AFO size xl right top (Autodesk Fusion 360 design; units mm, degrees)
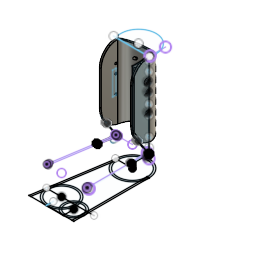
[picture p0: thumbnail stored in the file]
part number: 2025-10-02-12-56-12-317
parameter "d73" = 49
parameter "d131" = 16
sketch "Sketch1" plane through (0, 0, 0) normal (0, 0, 1) x axis (1, 0, 0)
  line L1 (28, -127.4) -> (-48, -127.4)
  line L2 (28, 0) -> (28, -127.4)
  line L3 (25, 0) -> (25, -127.4)
  line L4 (28, 0) -> (25, 0)
  line L5 (-18.603, -127.4) -> (-18.603, -115.6)
  line L6 (10.5, -127.4) -> (10.5, -109.9)
  line L7 (10.5, -127.4) -> (-18.603, -127.4)
  line L8 (36.7314, -101.9) -> (-43.9969, -101.9)
  line L9 (0, 0) -> (-28.984, 0)
  line L10 (-45, -127.4) -> (-25, 0)
  line L11 (-40.9969, -101.9) -> (-44.0794, -101.4161)
  line L12 (-48, -127.4) -> (-28, 0)
  line L13 (-43.6846, -101.9) -> (-43.6828, -102.2021)
  circle C1 centre (0, 0) radius 28
  circle C2 centre (0, 0) radius 25
  circle C3 centre (10.5, -109.9) radius 17.5
  circle C4 centre (-18.1846, -101.9) radius 22.5
  circle C5 centre (10.5, -109.9) radius 14.5
  circle C6 centre (-18.1846, -101.9) radius 25.5
  point P1 (0, 0)
  point P2 (0, 0)
  point P5 (28, 0)
  point P6 (0, 0)
  point P7 (25, 0)
  point P8 (25, -127.4)
  point P13 (-18.603, -127.4)
  point P11 (10.5, -109.9)
  point P14 (10.5, -109.9)
  point P15 (10.5, -127.4)
  point P20 (-25, 0)
  point P21 (-45, -127.4)
  point P22 (-40.9969, -101.9)
  point P10 (-18.1846, -101.9)
  point P25 (-28, 0)
  point P16 (-43.9969, -101.9)
  point P26 (-43.6828, -102.2021)
  point P27 (-43.6846, -101.9)
  point P19 (0, 0)
  coincident P1 P2
  coincident C1 P5
  tangent C1 L2
  perpendicular L1 L2
  coincident P1 P6
  vertical L3
  coincident C2 P7
  perpendicular L2 L4
  coincident L1 P8
  tangent L2 C3
  tangent L1 C3
  concentric C3 C5
  tangent L3 C5
  coincident L1 P13
  perpendicular L1 L5
  coincident P11 P14
  coincident L1 P15
  coincident C3 P15
  perpendicular L1 L6
  perpendicular L5 L8
  horizontal L9
  coincident C2 P20
  coincident L9 P20
  coincident L1 P21
  coincident L10 P22
  coincident L8 P22
  parallel L2 L3
  coincident P10 L8
  concentric C4 C6
  coincident L9 P25
  coincident C1 P25
  parallel L10 L12
  coincident P16 L12
  coincident C6 P26
  coincident L8 P27
  coincident C6 P27
  coincident P1 P19
  tangent L1 C6
  tangent C6 L12
  perpendicular L11 L12
  dimension "d2" diameter C1 = 56 (= "d57 + ( 3 * 2 ) * 1 mm")
  dimension "d4" distance P2 L1 = 127.4 (= "152.4 mm - 25 mm")
  dimension "d57" diameter C2 = 50
  dimension "d74" diameter C3 = 35
  dimension "d252" diameter C4 = 45 (= "d73 - 4 mm")
  dimension "d322" distance P8 P21 = 70
  dimension "d323" diameter C6 = 51 (= "d252 + 6 mm")
extrude "Extrude1" new body sketch "Sketch1" profile of C1 L2 L3 L4 C3 L8 L9 L10 L11 C6 L12 along normal blind 35
extrude "Extrude2" add sketch "Sketch1" profile of C1 L1 L2 C2 L3 C3 C4 C5 L5 L6 L7 L8 L10 L11 C6 L13 along normal blind 3
extrude "Extrude15" new body sketch "Sketch1" profile of C1 C2 L4 L9 along normal blind 178
combine "Combine2"
work_plane "WorkPlane1" RotateAngle -90
fillet "Fillet69" radius 1 1
sketch "Sketch23" plane through (28, 0, 0) normal (1, 0, 0) x axis (0, 1, 0)
  line L1 (-28, 78) -> (0, 35)
  line L2 (-28, 178) -> (-28, 78)
  line L3 (0, 178) -> (-28, 178)
  line L4 (0, 35) -> (0, 178)
  circle C1 centre (-3, 143) radius 1.75
  point P5 (0, 178)
  point P6 (0, 178)
  point P2 (0, 35)
  point P8 (0, 35)
  point P4 (-28, 178)
  point P3 (-28, 78)
  point P7 (-3, 143)
  horizontal L3
  perpendicular L3 L4
  coincident P5 P6
  coincident P2 P8
  parallel L2 L4
  dimension "d253" distance P4 P5 = 28
  dimension "d254" distance P3 P4 = 100
  dimension "d255" diameter C1 = 3.5
  dimension "d256" distance L3 P7 = 35
  dimension "d257" distance L2 P7 = 25
extrude "Extrude18" add sketch "Sketch23" against normal blind 3
mirror "Mirror1" mirrorStitchTolerance 0.1
sketch "Sketch24" plane through (0, 16.0046, 10.4216) normal (0, -0.838, -0.5457) x axis (1, 0, 0)
  line L1 (-25, 80.6427) -> (-25, 29.3299)
  line L2 (-28, 80.6427) -> (-25, 80.6427)
  line L3 (-28, 29.3299) -> (-28, 80.6427)
  line L4 (-25, 62.182) -> (-28, 62.182)
  line L5 (-28, 30.2476) -> (-25, 30.2476)
  line L6 (-28, 30.2476) -> (-28, 62.182)
  line L7 (-25, 62.182) -> (-25, 30.2476)
  line L8 (-25, 29.3299) -> (-28, 29.3299)
  point P6 (-28, 62.182)
  point P7 (-25, 62.182)
  point P8 (-25, 30.2476)
  point P9 (-28, 30.2476)
  coincident L3 P6
  coincident L1 P7
  perpendicular L1 L4
  coincident L1 P8
  coincident L3 P9
  perpendicular L3 L5
sketch "Sketch25" plane through (0, 0, 35) normal (0, 0, 1) x axis (-1, 0, 0)
  line L1 (24.843, -1) -> (27.843, -1)
  line L2 (29.5678, 29.0967) -> (24.843, -1)
  line L3 (32.4956, 28.637) -> (29.5678, 29.0967)
  line L4 (32.4956, 28.637) -> (27.843, -1)
  line L5 (0, 0) -> (28.984, 0)
  line L6 (43.3761, 97.9455) -> (28, 0)
  line L7 (25, 0) -> (40.9969, 101.9)
  line L8 (28, 0) -> (25, 0)
  line L9 (40.9969, 101.9) -> (43.6811, 101.4786)
  arc A1 centre (18.1846, 101.9) radius 25.5 clockwise from (43.6811, 101.4786) to (43.3761, 97.9455)
  point P5 (32.4956, 28.637)
  point P4 (29.5678, 29.0967)
  point P15 (28, 0)
  point P8 (25, 0)
  point P2 (27.843, -1)
  horizontal L1
  coincident P5 L6
  coincident P4 L7
  coincident L4 P15
  coincident L2 P8
  perpendicular L3 L4
  dimension "d280" distance P2 P5 = 30
  dimension "d281" distance L1 L5 = 1
loft "Loft1" sketch "Sketch24" + "Sketch25"
sketch "Sketch26" plane through (0, 0, 35) normal (0, 0, 1) x axis (-1, 0, 0)
  line L1 (-28, 0) -> (-28, 101.9)
  line L2 (-25, 0) -> (-28, 0)
  line L3 (-28, -1) -> (-25, -1)
  line L4 (-28, -1) -> (-28, 29)
  line L5 (-25, 29) -> (-28, 29)
  line L6 (-25, -1) -> (-25, 29)
  line L7 (-28, 101.9) -> (-25, 101.9)
  line L8 (-25, 101.9) -> (-25, 0)
  point P5 (-28, -1)
  point P6 (-28, 29)
  point P7 (-25, 29)
  coincident L1 P5
  perpendicular L1 L3
  coincident L1 P6
  coincident P7 L8
  dimension "d278" distance P5 P6 = 30
  dimension "d279" distance L2 L3 = 1
sketch "Sketch27" plane through (0, 16.0046, 10.4216) normal (0, -0.838, -0.5457) x axis (1, 0, 0)
  line L1 (28, 80.6427) -> (28, 29.3299)
  line L2 (25, 80.6427) -> (28, 80.6427)
  line L3 (25, 29.3299) -> (25, 80.6427)
  line L4 (28, 29.3299) -> (25, 29.3299)
  line L5 (28, 63.1164) -> (25, 63.1164)
  line L6 (28, 32.1164) -> (28, 63.1164)
  line L7 (28, 32.1164) -> (25, 32.1164)
  line L8 (25, 63.1164) -> (25, 32.1164)
  point P6 (25, 63.1164)
  point P7 (28, 63.1164)
  point P8 (28, 32.1164)
  point P9 (25, 32.1164)
  coincident L3 P6
  coincident L1 P7
  perpendicular L1 L5
  coincident L1 P8
  coincident L3 P9
  perpendicular L6 L7
  dimension "d282" distance P7 P8 = 31
loft "Loft2" sketch "Sketch27" + "Sketch26"
work_plane "WorkPlane4" AlongDistance 28 (= "25 mm + 3 mm")
sketch "Sketch9" plane through (0, 28, 0) normal (0, 1, 0) x axis (1, 0, 0)
  circle C1 centre (0, -16) radius 2.25
  circle C2 centre (0, -32) radius 2.25
  circle C3 centre (0, -64) radius 2.25
  circle C4 centre (0, -96) radius 2.25
  circle C5 centre (0, -80) radius 2.25
  circle C6 centre (0, -112) radius 2.25
  circle C7 centre (0, -128) radius 2.25
  circle C8 centre (0, -144) radius 2.25
  point P2 (0, -16)
  point P7 (0, 0)
  point P3 (0, -32)
  point P4 (0, -64)
  point P6 (0, -80)
  point P5 (0, -96)
  point P8 (0, -112)
  point P9 (0, -128)
  point P10 (0, -144)
  dimension "d123" diameter C1 = 4.5
  dimension "d124" diameter C2 = 4.5
  dimension "d126" diameter C3 = 4.5
  dimension "d127" diameter C4 = 4.5
  dimension "d128" diameter C5 = 4.5
  dimension "d129" distance P2 P7 = 16
  dimension "d130" distance P2 P3 = 16
  dimension "d133" distance P4 P6 = 16 (= "d131")
  dimension "d134" distance P5 P6 = 16 (= "d131")
  dimension "d291" diameter C6 = 4.5
  dimension "d292" distance P5 P8 = 16 (= "d131")
  dimension "d293" distance P8 P9 = 16 (= "d130")
  dimension "d294" diameter C7 = 4.5
  dimension "d295" diameter C8 = 4.5
  dimension "d296" distance P9 P10 = 16 (= "d131")
extrude "Extrude20" cut sketch "Sketch9" against normal blind 30
path_pattern "PathPattern3" PathPatternDelta 88.0394
fillet "Fillet51" radius 7 15
fillet "Fillet52" radius 130 130
sphere_primitive "SpherePrimitive3" Diameter 55
move_face "MoveFace3"
boundary_fill "BoundaryFill2"
offset_faces "OffsetFaces2" distance 3
shell "Shell7" innerThickness 2.99
fillet "Fillet74" radius 10 15
hole "Hole6" HoleDepth 106.033 HoleDiameter 3.5 TipAngle 118
hole "Hole7" HoleDepth 106.033 HoleDiameter 3.5 TipAngle 118
work_plane "WorkPlane5" AlongDistance 100
work_plane "WorkPlane6" AlongDistance 51.6037
fillet "Fillet76" radius 30
fillet "Fillet79" radius 25
fillet "Fillet83" radius 22
fillet "Fillet85" radius 30 30
fillet "Fillet86" radius 45
split "Split1"
work_plane "WorkPlane7" AlongDistance -28 (= "-( 56 / 2 ) * 1 mm")
sketch "Sketch35" plane through (-28, 0, 0) normal (1, 0, 0) x axis (0, 1, 0)
  circle C1 centre (-2.7874, 31.4508) radius 6
  dimension "d426" diameter C1 = 12
extrude "Extrude22" add sketch "Sketch35" against normal blind 2
fillet "Fillet87" radius 35
sketch "Sketch33" plane through (27.99, 0, 0) normal (1, 0, 0) x axis (0, 1, 0)
  line L1 (0, 139.3302) -> (0, 52.395)
  line L2 (0, 175.01) -> (0, 146.6698)
  line L3 (-11.056, 175.01) -> (0, 175.01)
  line L4 (-25.01, 78.8877) -> (-25.01, 161.056)
  line L5 (-15.1078, 63.6808) -> (-25.01, 78.8877)
  line L6 (-16.1988, 60.7566) -> (-15.1078, 63.6808)
  line L7 (2, 178) -> (28, 178)
  arc A1 centre (7.4005, 86.6037) radius 35 clockwise from (0, 52.395) to (-16.1988, 60.7566)
  arc A2 centre (-3, 143) radius 4.74 clockwise from (0, 139.3302) to (0, 146.6698)
  arc A3 centre (2, 148) radius 30 clockwise from (-25.01, 161.056) to (-11.056, 175.01)
  circle C1 centre (-3, 128) radius 1.75
  circle C2 centre (-3, 98) radius 1.75
  circle C3 centre (-3, 32) radius 1.75
  point P16 (-3, 128)
  point P17 (-3, 98)
  point P18 (-3, 32)
  vertical P16 P17
  vertical P17 P18
  dimension "d413" diameter C1 = 3.5
  dimension "d414" distance P16 P17 = 30
  dimension "d415" diameter C3 = 3.5
  dimension "d416" distance P17 P18 = 66
  dimension "d417" distance P16 L7 = 50
  dimension "d418" distance L1 P16 = 3
  dimension "d480" diameter C2 = 3.5
extrude "Extrude21" cut sketch "Sketch33" profile of C1 C2 C3 against normal blind 133.937
fillet "Fillet88" radius 36
sketch "Sketch37" plane through (-28, 0, 0) normal (1, 0, 0) x axis (0, 1, 0)
fillet "Fillet98" radius 48
fillet "Fillet99" radius 48
sketch "Sketch38" plane through (-28, 0, 0) normal (1, 0, 0) x axis (0, 1, 0)
  line L1 (-5.5406, 132.8689) -> (0, 132.8689)
  line L2 (-5.5406, 93.572) -> (-5.5406, 132.8689)
  line L3 (0, 93.572) -> (-5.5406, 93.572)
  line L4 (0, 132.8689) -> (0, 93.572)
  horizontal L1
  vertical L2
  horizontal L3
  vertical L4
extrude "Extrude24" add sketch "Sketch38" along normal blind 1 and against normal blind 2
fillet "Fillet91" radius 2 2 2 2
fillet "Fillet92" radius 0.5
extrude "Extrude25" cut sketch "Sketch33" profile of C1 C2 against normal blind 188.494
work_plane "WorkPlane8" AlongDistance 178
sketch "Sketch39" plane through (0, 0, 178) normal (0, 0, 1) x axis (1, 0, 0)
  line L1 (-25, 0) -> (25, 0)
  line L2 (30, 0) -> (25, 0)
  line L3 (-32, 0) -> (-25, 0)
  arc A1 centre (0, 10.2) radius 29.8 clockwise from (-28, 0) to (28, 0)
  point P7 (-28, 0)
  horizontal L1
  parallel L1 L2
  parallel L1 L3
  coincident L3 P7
revolve "Revolve2" sketch "Sketch39" AlongAngle -30
fillet "Fillet95" radius 20 20
fillet "Fillet101" radius 1
fillet "Fillet97" radius 1.5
